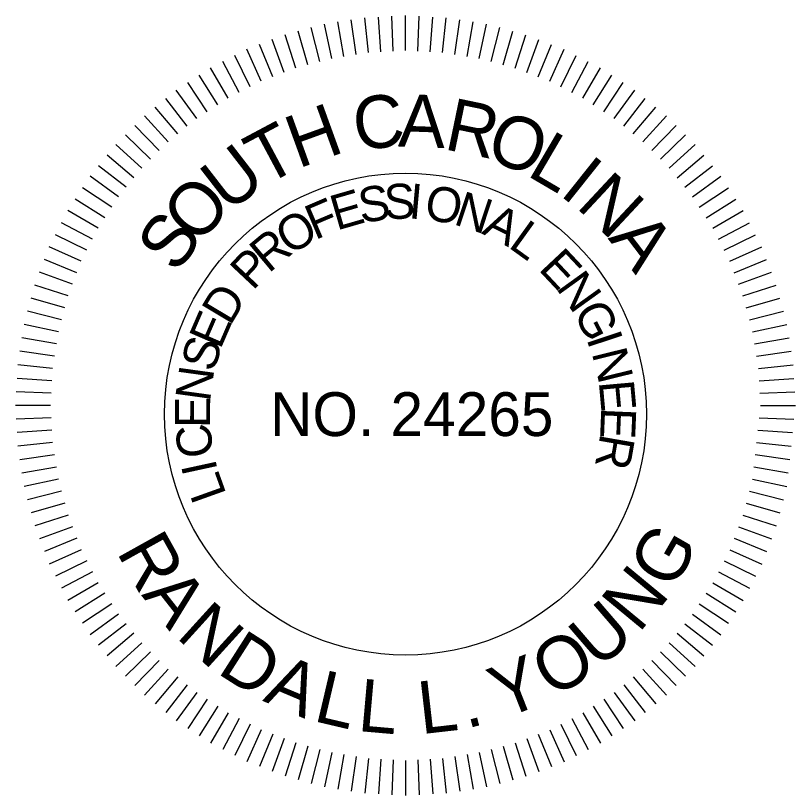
# Model space of a CAD drawing. Extents: x 1964849 to 1967422, y 1116563 to 1122211.
# Drawn here: x 1967342.1 to 1967421.3, y 1121681.4 to 1121760.6 of the extents above; entities that cross this region are included whole.
import ezdxf

# ---------------------------------------------------------------- set-up
doc = ezdxf.new("R2010")
doc.units = 0
doc.layers.add('RD_TX_PEShield', color=7, linetype='Continuous')

msp = doc.modelspace()

# ---------------------------------------------------------------- linework, layer by layer
at = {"layer": 'RD_TX_PEShield'}
for p, q in [((1967376.676, 1121756.687), (1967376.181, 1121760.208)), ((1967376.676, 1121756.687), (1967376.181, 1121760.208)), ((1967377.918, 1121756.884), (1967377.546, 1121760.424)), ((1967377.918, 1121756.884), (1967377.546, 1121760.424)), ((1967379.175, 1121756.949), (1967378.927, 1121760.496)), ((1967379.175, 1121756.949), (1967378.927, 1121760.496)), ((1967380.43, 1121757.015), (1967380.306, 1121760.569)), ((1967380.43, 1121757.015), (1967380.306, 1121760.569)), ((1967381.686, 1121757.081), (1967381.686, 1121760.641)), ((1967381.686, 1121757.081), (1967381.686, 1121760.641)), ((1967382.943, 1121757.015), (1967383.067, 1121760.569)), ((1967382.943, 1121757.015), (1967383.067, 1121760.569)), ((1967384.198, 1121756.949), (1967384.446, 1121760.496)), ((1967384.198, 1121756.949), (1967384.446, 1121760.496)), ((1967385.454, 1121756.884), (1967385.826, 1121760.424)), ((1967385.454, 1121756.884), (1967385.826, 1121760.424)), ((1967386.697, 1121756.687), (1967387.191, 1121760.208)), ((1967386.697, 1121756.687), (1967387.191, 1121760.208)), ((1967372.977, 1121755.968), (1967372.117, 1121759.418)), ((1967372.977, 1121755.968), (1967372.117, 1121759.418)), ((1967374.192, 1121756.293), (1967373.452, 1121759.776)), ((1967374.192, 1121756.293), (1967373.452, 1121759.776)), ((1967375.435, 1121756.49), (1967374.817, 1121759.992)), ((1967375.435, 1121756.49), (1967374.817, 1121759.992)), ((1967387.938, 1121756.49), (1967388.555, 1121759.992)), ((1967387.938, 1121756.49), (1967388.555, 1121759.992)), ((1967389.18, 1121756.293), (1967389.921, 1121759.776)), ((1967389.18, 1121756.293), (1967389.921, 1121759.776)), ((1967389.18, 1121756.293), (1967389.921, 1121759.776)), ((1967390.396, 1121755.968), (1967391.256, 1121759.418)), ((1967390.396, 1121755.968), (1967391.256, 1121759.418)), ((1967390.396, 1121755.968), (1967391.256, 1121759.418)), ((1967370.548, 1121755.317), (1967369.448, 1121758.703)), ((1967370.548, 1121755.317), (1967369.448, 1121758.703)), ((1967371.763, 1121755.642), (1967370.783, 1121759.06)), ((1967371.763, 1121755.642), (1967370.783, 1121759.06)), ((1967391.609, 1121755.642), (1967392.59, 1121759.06)), ((1967391.609, 1121755.642), (1967392.59, 1121759.06)), ((1967391.609, 1121755.642), (1967392.59, 1121759.06)), ((1967392.825, 1121755.317), (1967393.925, 1121758.703)), ((1967392.825, 1121755.317), (1967393.925, 1121758.703)), ((1967392.825, 1121755.317), (1967393.925, 1121758.703)), ((1967369.373, 1121754.866), (1967368.157, 1121758.207)), ((1967369.373, 1121754.866), (1967368.157, 1121758.207)), ((1967393.999, 1121754.866), (1967395.215, 1121758.207)), ((1967393.999, 1121754.866), (1967395.215, 1121758.207)), ((1967393.999, 1121754.866), (1967395.215, 1121758.207)), ((1967367.025, 1121753.965), (1967365.577, 1121757.217)), ((1967367.025, 1121753.965), (1967365.577, 1121757.217)), ((1967368.2, 1121754.416), (1967366.868, 1121757.712)), ((1967368.2, 1121754.416), (1967366.868, 1121757.712)), ((1967395.172, 1121754.416), (1967396.504, 1121757.712)), ((1967395.172, 1121754.416), (1967396.504, 1121757.712)), ((1967395.172, 1121754.416), (1967396.504, 1121757.712)), ((1967396.347, 1121753.965), (1967397.795, 1121757.217)), ((1967396.347, 1121753.965), (1967397.795, 1121757.217)), ((1967396.347, 1121753.965), (1967397.795, 1121757.217)), ((1967365.904, 1121753.394), (1967364.346, 1121756.589)), ((1967365.904, 1121753.394), (1967364.346, 1121756.589)), ((1967397.468, 1121753.394), (1967399.027, 1121756.589)), ((1967397.468, 1121753.394), (1967399.027, 1121756.589)), ((1967397.468, 1121753.394), (1967399.027, 1121756.589)), ((1967364.785, 1121752.823), (1967363.115, 1121755.963)), ((1967364.785, 1121752.823), (1967363.115, 1121755.963)), ((1967398.588, 1121752.823), (1967400.257, 1121755.963)), ((1967398.588, 1121752.823), (1967400.257, 1121755.963)), ((1967398.588, 1121752.823), (1967400.257, 1121755.963)), ((1967363.664, 1121752.252), (1967361.884, 1121755.335)), ((1967363.664, 1121752.252), (1967361.884, 1121755.335)), ((1967399.709, 1121752.252), (1967401.489, 1121755.335)), ((1967399.709, 1121752.252), (1967401.489, 1121755.335)), ((1967399.709, 1121752.252), (1967401.489, 1121755.335)), ((1967361.555, 1121750.882), (1967359.566, 1121753.83)), ((1967361.555, 1121750.882), (1967359.566, 1121753.83)), ((1967362.609, 1121751.567), (1967360.724, 1121754.582)), ((1967362.609, 1121751.567), (1967360.724, 1121754.582)), ((1967400.764, 1121751.567), (1967402.648, 1121754.582)), ((1967400.764, 1121751.567), (1967402.648, 1121754.582)), ((1967400.764, 1121751.567), (1967402.648, 1121754.582)), ((1967401.818, 1121750.882), (1967403.806, 1121753.83)), ((1967401.818, 1121750.882), (1967403.806, 1121753.83)), ((1967401.818, 1121750.882), (1967403.806, 1121753.83)), ((1967360.499, 1121750.197), (1967358.407, 1121753.077)), ((1967360.499, 1121750.197), (1967358.407, 1121753.077)), ((1967402.873, 1121750.197), (1967404.965, 1121753.077)), ((1967402.873, 1121750.197), (1967404.965, 1121753.077)), ((1967402.873, 1121750.197), (1967404.965, 1121753.077)), ((1967359.522, 1121749.405), (1967357.333, 1121752.207)), ((1967359.522, 1121749.405), (1967357.333, 1121752.207)), ((1967403.851, 1121749.405), (1967406.04, 1121752.207)), ((1967403.851, 1121749.405), (1967406.04, 1121752.207)), ((1967403.851, 1121749.405), (1967406.04, 1121752.207)), ((1967358.545, 1121748.614), (1967356.26, 1121751.338)), ((1967358.545, 1121748.614), (1967356.26, 1121751.338)), ((1967404.827, 1121748.614), (1967407.113, 1121751.338)), ((1967404.827, 1121748.614), (1967407.113, 1121751.338)), ((1967404.827, 1121748.614), (1967407.113, 1121751.338)), ((1967357.567, 1121747.823), (1967355.185, 1121750.468)), ((1967357.567, 1121747.823), (1967355.185, 1121750.468)), ((1967405.805, 1121747.823), (1967408.187, 1121750.468)), ((1967405.805, 1121747.823), (1967408.187, 1121750.468)), ((1967405.805, 1121747.823), (1967408.187, 1121750.468)), ((1967356.678, 1121746.933), (1967354.208, 1121749.491)), ((1967356.678, 1121746.933), (1967354.208, 1121749.491)), ((1967406.695, 1121746.933), (1967409.165, 1121749.491)), ((1967406.695, 1121746.933), (1967409.165, 1121749.491)), ((1967406.695, 1121746.933), (1967409.165, 1121749.491)), ((1967355.789, 1121746.044), (1967353.231, 1121748.514)), ((1967355.789, 1121746.044), (1967353.231, 1121748.514)), ((1967407.583, 1121746.044), (1967410.141, 1121748.514)), ((1967407.583, 1121746.044), (1967410.141, 1121748.514)), ((1967407.583, 1121746.044), (1967410.141, 1121748.514)), ((1967354.9, 1121745.155), (1967352.254, 1121747.537)), ((1967354.9, 1121745.155), (1967352.254, 1121747.537)), ((1967408.473, 1121745.155), (1967411.118, 1121747.537)), ((1967408.473, 1121745.155), (1967411.118, 1121747.537)), ((1967408.473, 1121745.155), (1967411.118, 1121747.537)), ((1967354.108, 1121744.177), (1967351.384, 1121746.463)), ((1967354.108, 1121744.177), (1967351.384, 1121746.463)), ((1967409.265, 1121744.177), (1967411.988, 1121746.463)), ((1967409.265, 1121744.177), (1967411.988, 1121746.463)), ((1967409.265, 1121744.177), (1967411.988, 1121746.463)), ((1967353.317, 1121743.2), (1967350.515, 1121745.39)), ((1967353.317, 1121743.2), (1967350.515, 1121745.39)), ((1967410.055, 1121743.2), (1967412.857, 1121745.39)), ((1967410.055, 1121743.2), (1967412.857, 1121745.39)), ((1967410.055, 1121743.2), (1967412.857, 1121745.39)), ((1967352.525, 1121742.223), (1967349.645, 1121744.315)), ((1967352.525, 1121742.223), (1967349.645, 1121744.315)), ((1967410.847, 1121742.223), (1967413.727, 1121744.315)), ((1967410.847, 1121742.223), (1967413.727, 1121744.315)), ((1967410.847, 1121742.223), (1967413.727, 1121744.315)), ((1967351.84, 1121741.168), (1967348.892, 1121743.156)), ((1967351.84, 1121741.168), (1967348.892, 1121743.156)), ((1967411.532, 1121741.168), (1967414.48, 1121743.156)), ((1967411.532, 1121741.168), (1967414.48, 1121743.156)), ((1967411.532, 1121741.168), (1967414.48, 1121743.156)), ((1967351.156, 1121740.114), (1967348.14, 1121741.998)), ((1967351.156, 1121740.114), (1967348.14, 1121741.998)), ((1967412.217, 1121740.114), (1967415.232, 1121741.998)), ((1967412.217, 1121740.114), (1967415.232, 1121741.998)), ((1967412.217, 1121740.114), (1967415.232, 1121741.998)), ((1967350.47, 1121739.058), (1967347.387, 1121740.838)), ((1967350.47, 1121739.058), (1967347.387, 1121740.838)), ((1967412.902, 1121739.058), (1967415.985, 1121740.838)), ((1967412.902, 1121739.058), (1967415.985, 1121740.838)), ((1967412.902, 1121739.058), (1967415.985, 1121740.838)), ((1967349.899, 1121737.937), (1967346.76, 1121739.607)), ((1967349.899, 1121737.937), (1967346.76, 1121739.607)), ((1967413.473, 1121737.937), (1967416.613, 1121739.607)), ((1967413.473, 1121737.937), (1967416.613, 1121739.607)), ((1967413.473, 1121737.937), (1967416.613, 1121739.607)), ((1967349.329, 1121736.818), (1967346.133, 1121738.377)), ((1967349.329, 1121736.818), (1967346.133, 1121738.377)), ((1967414.044, 1121736.818), (1967417.24, 1121738.377)), ((1967414.044, 1121736.818), (1967417.24, 1121738.377)), ((1967414.044, 1121736.818), (1967417.24, 1121738.377)), ((1967348.757, 1121735.697), (1967345.505, 1121737.145)), ((1967348.757, 1121735.697), (1967345.505, 1121737.145)), ((1967414.615, 1121735.697), (1967417.867, 1121737.145)), ((1967414.615, 1121735.697), (1967417.867, 1121737.145)), ((1967414.615, 1121735.697), (1967417.867, 1121737.145)), ((1967348.307, 1121734.522), (1967345.01, 1121735.854)), ((1967348.307, 1121734.522), (1967345.01, 1121735.854)), ((1967415.066, 1121734.522), (1967418.363, 1121735.854)), ((1967415.066, 1121734.522), (1967418.363, 1121735.854)), ((1967415.066, 1121734.522), (1967418.363, 1121735.854)), ((1967347.856, 1121733.349), (1967344.515, 1121734.565)), ((1967347.856, 1121733.349), (1967344.515, 1121734.565)), ((1967415.516, 1121733.349), (1967418.857, 1121734.565)), ((1967415.516, 1121733.349), (1967418.857, 1121734.565)), ((1967415.516, 1121733.349), (1967418.857, 1121734.565)), ((1967347.405, 1121732.174), (1967344.02, 1121733.275)), ((1967347.405, 1121732.174), (1967344.02, 1121733.275)), ((1967415.967, 1121732.174), (1967419.353, 1121733.275)), ((1967415.967, 1121732.174), (1967419.353, 1121733.275)), ((1967415.967, 1121732.174), (1967419.353, 1121733.275)), ((1967347.08, 1121730.959), (1967343.662, 1121731.939)), ((1967347.08, 1121730.959), (1967343.662, 1121731.939)), ((1967416.293, 1121730.959), (1967419.711, 1121731.939)), ((1967416.293, 1121730.959), (1967419.711, 1121731.939)), ((1967416.293, 1121730.959), (1967419.711, 1121731.939)), ((1967346.754, 1121729.745), (1967343.304, 1121730.606)), ((1967346.754, 1121729.745), (1967343.304, 1121730.606)), ((1967416.618, 1121729.745), (1967420.068, 1121730.606)), ((1967416.618, 1121729.745), (1967420.068, 1121730.606)), ((1967416.618, 1121729.745), (1967420.068, 1121730.606)), ((1967346.429, 1121728.53), (1967342.947, 1121729.27)), ((1967346.429, 1121728.53), (1967342.947, 1121729.27)), ((1967416.944, 1121728.53), (1967420.426, 1121729.27)), ((1967416.944, 1121728.53), (1967420.426, 1121729.27)), ((1967416.944, 1121728.53), (1967420.426, 1121729.27)), ((1967346.232, 1121727.287), (1967342.73, 1121727.905)), ((1967346.232, 1121727.287), (1967342.73, 1121727.905)), ((1967417.14, 1121727.287), (1967420.642, 1121727.905)), ((1967417.14, 1121727.287), (1967420.642, 1121727.905)), ((1967417.14, 1121727.287), (1967420.642, 1121727.905)), ((1967346.035, 1121726.046), (1967342.514, 1121726.541)), ((1967346.035, 1121726.046), (1967342.514, 1121726.541)), ((1967417.337, 1121726.046), (1967420.858, 1121726.541)), ((1967417.337, 1121726.046), (1967420.858, 1121726.541)), ((1967417.337, 1121726.046), (1967420.858, 1121726.541)), ((1967345.839, 1121724.804), (1967342.298, 1121725.176)), ((1967345.839, 1121724.804), (1967342.298, 1121725.176)), ((1967417.534, 1121724.804), (1967421.074, 1121725.176)), ((1967417.534, 1121724.804), (1967421.074, 1121725.176)), ((1967417.534, 1121724.804), (1967421.074, 1121725.176)), ((1967345.773, 1121723.547), (1967342.226, 1121723.795)), ((1967345.773, 1121723.547), (1967342.226, 1121723.795)), ((1967417.6, 1121723.547), (1967421.147, 1121723.795)), ((1967417.6, 1121723.547), (1967421.147, 1121723.795)), ((1967417.6, 1121723.547), (1967421.147, 1121723.795)), ((1967345.707, 1121722.292), (1967342.154, 1121722.416)), ((1967345.707, 1121722.292), (1967342.154, 1121722.416)), ((1967417.665, 1121722.292), (1967421.219, 1121722.416)), ((1967417.665, 1121722.292), (1967421.219, 1121722.416)), ((1967417.665, 1121722.292), (1967421.219, 1121722.416)), ((1967345.641, 1121721.036), (1967342.081, 1121721.036)), ((1967345.641, 1121721.036), (1967342.081, 1121721.036)), ((1967417.731, 1121721.036), (1967421.291, 1121721.036)), ((1967417.731, 1121721.036), (1967421.291, 1121721.036)), ((1967417.731, 1121721.036), (1967421.291, 1121721.036)), ((1967345.707, 1121719.78), (1967342.154, 1121719.655)), ((1967345.707, 1121719.78), (1967342.154, 1121719.655)), ((1967417.599, 1121719.782), (1967421.146, 1121719.658)), ((1967417.599, 1121719.782), (1967421.146, 1121719.658)), ((1967345.773, 1121718.525), (1967342.226, 1121718.277)), ((1967345.773, 1121718.525), (1967342.226, 1121718.277)), ((1967417.468, 1121718.534), (1967421.002, 1121718.287)), ((1967417.468, 1121718.534), (1967421.002, 1121718.287)), ((1967345.839, 1121717.268), (1967342.298, 1121716.896)), ((1967345.839, 1121717.268), (1967342.298, 1121716.896)), ((1967417.337, 1121717.289), (1967420.858, 1121716.919)), ((1967417.337, 1121717.289), (1967420.858, 1121716.919)), ((1967346.035, 1121716.026), (1967342.514, 1121715.531)), ((1967346.035, 1121716.026), (1967342.514, 1121715.531)), ((1967417.207, 1121716.044), (1967420.715, 1121715.551)), ((1967417.207, 1121716.044), (1967420.715, 1121715.551)), ((1967346.232, 1121714.784), (1967342.73, 1121714.167)), ((1967346.232, 1121714.784), (1967342.73, 1121714.167)), ((1967417.075, 1121714.796), (1967420.571, 1121714.18)), ((1967417.075, 1121714.796), (1967420.571, 1121714.18)), ((1967346.429, 1121713.542), (1967342.947, 1121712.802)), ((1967346.429, 1121713.542), (1967342.947, 1121712.802)), ((1967416.944, 1121713.542), (1967420.426, 1121712.802)), ((1967416.944, 1121713.542), (1967420.426, 1121712.802)), ((1967346.754, 1121712.327), (1967343.304, 1121711.466)), ((1967346.754, 1121712.327), (1967343.304, 1121711.466)), ((1967416.618, 1121712.327), (1967420.068, 1121711.466)), ((1967416.618, 1121712.327), (1967420.068, 1121711.466)), ((1967347.08, 1121711.113), (1967343.662, 1121710.133)), ((1967347.08, 1121711.113), (1967343.662, 1121710.133)), ((1967416.293, 1121711.113), (1967419.711, 1121710.133)), ((1967416.293, 1121711.113), (1967419.711, 1121710.133)), ((1967347.405, 1121709.897), (1967344.02, 1121708.797)), ((1967415.967, 1121709.897), (1967419.353, 1121708.797)), ((1967415.967, 1121709.897), (1967419.353, 1121708.797)), ((1967347.856, 1121708.723), (1967344.515, 1121707.507)), ((1967347.856, 1121708.723), (1967344.515, 1121707.507)), ((1967415.516, 1121708.723), (1967418.857, 1121707.507)), ((1967415.516, 1121708.723), (1967418.857, 1121707.507)), ((1967348.307, 1121707.55), (1967345.01, 1121706.218)), ((1967348.307, 1121707.55), (1967345.01, 1121706.218)), ((1967415.066, 1121707.55), (1967418.363, 1121706.218)), ((1967415.066, 1121707.55), (1967418.363, 1121706.218)), ((1967348.757, 1121706.375), (1967345.505, 1121704.927)), ((1967348.757, 1121706.375), (1967345.505, 1121704.927)), ((1967414.615, 1121706.375), (1967417.867, 1121704.927)), ((1967414.615, 1121706.375), (1967417.867, 1121704.927)), ((1967349.329, 1121705.254), (1967346.133, 1121703.695)), ((1967349.329, 1121705.254), (1967346.133, 1121703.695)), ((1967414.044, 1121705.254), (1967417.24, 1121703.695)), ((1967414.044, 1121705.254), (1967417.24, 1121703.695)), ((1967349.899, 1121704.134), (1967346.76, 1121702.465)), ((1967349.899, 1121704.134), (1967346.76, 1121702.465)), ((1967413.473, 1121704.134), (1967416.613, 1121702.465)), ((1967413.473, 1121704.134), (1967416.613, 1121702.465)), ((1967350.47, 1121703.013), (1967347.387, 1121701.233)), ((1967350.47, 1121703.013), (1967347.387, 1121701.233)), ((1967412.902, 1121703.013), (1967415.985, 1121701.233)), ((1967412.902, 1121703.013), (1967415.985, 1121701.233)), ((1967351.156, 1121701.958), (1967348.14, 1121700.074)), ((1967351.156, 1121701.958), (1967348.14, 1121700.074)), ((1967412.217, 1121701.958), (1967415.232, 1121700.074)), ((1967412.217, 1121701.958), (1967415.232, 1121700.074)), ((1967351.84, 1121700.904), (1967348.892, 1121698.916)), ((1967351.84, 1121700.904), (1967348.892, 1121698.916)), ((1967411.532, 1121700.904), (1967414.48, 1121698.916)), ((1967411.532, 1121700.904), (1967414.48, 1121698.916)), ((1967352.525, 1121699.849), (1967349.645, 1121697.757)), ((1967352.525, 1121699.849), (1967349.645, 1121697.757)), ((1967410.847, 1121699.849), (1967413.727, 1121697.757)), ((1967410.847, 1121699.849), (1967413.727, 1121697.757)), ((1967353.317, 1121698.871), (1967350.515, 1121696.682)), ((1967353.317, 1121698.871), (1967350.515, 1121696.682)), ((1967410.055, 1121698.871), (1967412.857, 1121696.682)), ((1967410.055, 1121698.871), (1967412.857, 1121696.682)), ((1967354.108, 1121697.895), (1967351.384, 1121695.609)), ((1967354.108, 1121697.895), (1967351.384, 1121695.609)), ((1967409.265, 1121697.895), (1967411.988, 1121695.609)), ((1967409.265, 1121697.895), (1967411.988, 1121695.609)), ((1967354.9, 1121696.917), (1967352.254, 1121694.535)), ((1967354.9, 1121696.917), (1967352.254, 1121694.535)), ((1967408.473, 1121696.917), (1967411.118, 1121694.535)), ((1967408.473, 1121696.917), (1967411.118, 1121694.535)), ((1967355.789, 1121696.028), (1967353.231, 1121693.558)), ((1967355.789, 1121696.028), (1967353.231, 1121693.558)), ((1967407.583, 1121696.028), (1967410.141, 1121693.558)), ((1967407.583, 1121696.028), (1967410.141, 1121693.558)), ((1967356.678, 1121695.139), (1967354.208, 1121692.581)), ((1967356.678, 1121695.139), (1967354.208, 1121692.581)), ((1967406.695, 1121695.139), (1967409.165, 1121692.581)), ((1967406.695, 1121695.139), (1967409.165, 1121692.581)), ((1967357.567, 1121694.249), (1967355.185, 1121691.604)), ((1967357.567, 1121694.249), (1967355.185, 1121691.604)), ((1967405.805, 1121694.249), (1967408.187, 1121691.604)), ((1967358.545, 1121693.458), (1967356.26, 1121690.734)), ((1967358.545, 1121693.458), (1967356.26, 1121690.734)), ((1967404.827, 1121693.458), (1967407.113, 1121690.734)), ((1967404.827, 1121693.458), (1967407.113, 1121690.734)), ((1967359.522, 1121692.667), (1967357.333, 1121689.865)), ((1967359.522, 1121692.667), (1967357.333, 1121689.865)), ((1967403.851, 1121692.667), (1967406.04, 1121689.865)), ((1967403.851, 1121692.667), (1967406.04, 1121689.865)), ((1967360.499, 1121691.875), (1967358.407, 1121688.995)), ((1967360.499, 1121691.875), (1967358.407, 1121688.995)), ((1967402.873, 1121691.875), (1967404.965, 1121688.995)), ((1967402.873, 1121691.875), (1967404.965, 1121688.995)), ((1967361.555, 1121691.19), (1967359.566, 1121688.242)), ((1967361.555, 1121691.19), (1967359.566, 1121688.242)), ((1967362.609, 1121690.505), (1967360.724, 1121687.49)), ((1967362.609, 1121690.505), (1967360.724, 1121687.49)), ((1967400.764, 1121690.505), (1967402.648, 1121687.49)), ((1967400.764, 1121690.505), (1967402.648, 1121687.49)), ((1967401.818, 1121691.19), (1967403.806, 1121688.242)), ((1967401.818, 1121691.19), (1967403.806, 1121688.242)), ((1967363.664, 1121689.82), (1967361.884, 1121686.737)), ((1967363.664, 1121689.82), (1967361.884, 1121686.737)), ((1967399.709, 1121689.82), (1967401.489, 1121686.737)), ((1967399.709, 1121689.82), (1967401.489, 1121686.737)), ((1967364.785, 1121689.249), (1967363.115, 1121686.109)), ((1967364.785, 1121689.249), (1967363.115, 1121686.109)), ((1967398.588, 1121689.249), (1967400.257, 1121686.109)), ((1967398.588, 1121689.249), (1967400.257, 1121686.109)), ((1967365.904, 1121688.678), (1967364.346, 1121685.483)), ((1967365.904, 1121688.678), (1967364.346, 1121685.483)), ((1967367.025, 1121688.107), (1967365.577, 1121684.855)), ((1967367.025, 1121688.107), (1967365.577, 1121684.855)), ((1967396.347, 1121688.107), (1967397.795, 1121684.855)), ((1967396.347, 1121688.107), (1967397.795, 1121684.855)), ((1967397.468, 1121688.678), (1967399.027, 1121685.483)), ((1967397.468, 1121688.678), (1967399.027, 1121685.483)), ((1967368.2, 1121687.656), (1967366.868, 1121684.36)), ((1967368.2, 1121687.656), (1967366.868, 1121684.36)), ((1967395.172, 1121687.656), (1967396.504, 1121684.36)), ((1967395.172, 1121687.656), (1967396.504, 1121684.36)), ((1967369.373, 1121687.206), (1967368.157, 1121683.865)), ((1967369.373, 1121687.206), (1967368.157, 1121683.865)), ((1967370.548, 1121686.755), (1967369.448, 1121683.369)), ((1967370.548, 1121686.755), (1967369.448, 1121683.369)), ((1967392.825, 1121686.755), (1967393.925, 1121683.369)), ((1967392.825, 1121686.755), (1967393.925, 1121683.369)), ((1967393.999, 1121687.206), (1967395.215, 1121683.865)), ((1967393.999, 1121687.206), (1967395.215, 1121683.865)), ((1967371.763, 1121686.43), (1967370.783, 1121683.012)), ((1967371.763, 1121686.43), (1967370.783, 1121683.012)), ((1967372.977, 1121686.104), (1967372.117, 1121682.654)), ((1967372.977, 1121686.104), (1967372.117, 1121682.654)), ((1967374.192, 1121685.779), (1967373.452, 1121682.296)), ((1967374.192, 1121685.779), (1967373.452, 1121682.296)), ((1967389.18, 1121685.779), (1967389.921, 1121682.296)), ((1967389.18, 1121685.779), (1967389.921, 1121682.296)), ((1967390.396, 1121686.104), (1967391.256, 1121682.654)), ((1967390.396, 1121686.104), (1967391.256, 1121682.654)), ((1967391.609, 1121686.43), (1967392.59, 1121683.012)), ((1967391.609, 1121686.43), (1967392.59, 1121683.012)), ((1967375.435, 1121685.582), (1967374.817, 1121682.08)), ((1967375.435, 1121685.582), (1967374.817, 1121682.08)), ((1967376.676, 1121685.385), (1967376.181, 1121681.864)), ((1967376.676, 1121685.385), (1967376.181, 1121681.864)), ((1967377.918, 1121685.188), (1967377.546, 1121681.648)), ((1967377.918, 1121685.188), (1967377.546, 1121681.648)), ((1967379.175, 1121685.123), (1967378.927, 1121681.576)), ((1967379.175, 1121685.123), (1967378.927, 1121681.576)), ((1967380.43, 1121685.057), (1967380.306, 1121681.503)), ((1967380.43, 1121685.057), (1967380.306, 1121681.503)), ((1967381.686, 1121684.991), (1967381.686, 1121681.431)), ((1967381.686, 1121684.991), (1967381.686, 1121681.431)), ((1967382.943, 1121685.057), (1967383.067, 1121681.503)), ((1967382.943, 1121685.057), (1967383.067, 1121681.503)), ((1967384.198, 1121685.123), (1967384.446, 1121681.576)), ((1967384.198, 1121685.123), (1967384.446, 1121681.576)), ((1967385.454, 1121685.188), (1967385.826, 1121681.648)), ((1967385.454, 1121685.188), (1967385.826, 1121681.648)), ((1967386.697, 1121685.385), (1967387.191, 1121681.864)), ((1967386.697, 1121685.385), (1967387.191, 1121681.864)), ((1967387.938, 1121685.582), (1967388.555, 1121682.08)), ((1967387.938, 1121685.582), (1967388.555, 1121682.08))]:
    msp.add_line(p, q, dxfattribs=at)
msp.add_circle((1967381.686, 1121720.158), 24.475, dxfattribs=at)

# ---------------------------------------------------------------- texts
for s, height, rotation, p in [('C', 5.34, 6.88322, (1967376.68, 1121746.896)), ('A', 5.34, 357.94482, (1967380.895, 1121747.349)), ('H', 5.34, 19.91024, (1967370.782, 1121745.079)), ('R', 5.34, 348.26699, (1967385.478, 1121747.095)), ('O', 5.34, 339.32858, (1967389.617, 1121746.178)), ('T', 5.34, 28.09472, (1967367.345, 1121743.273)), ('L', 5.34, 329.65075, (1967393.878, 1121744.475)), ('U', 5.34, 37.77255, (1967363.664, 1121740.533)), ('I', 5.34, 321.46627, (1967397.216, 1121742.492)), ('N', 5.34, 317.00069, (1967398.908, 1121741.215)), ('O', 5.34, 47.45038, (1967360.495, 1121737.214)), ('S', 3.56, 1.78995, (1967379.536, 1121739.948)), ('I', 3.56, 354.88899, (1967381.93, 1121740.062)), ('E', 3.56, 16.18428, (1967374.684, 1121738.792)), ('S', 3.56, 8.69092, (1967377.174, 1121739.546)), ('O', 3.56, 350.40454, (1967383.485, 1121739.982)), ('N', 3.56, 341.70291, (1967386.464, 1121739.482)), ('F', 3.56, 23.08525, (1967372.496, 1121737.816)), ('S', 5.34, 54.90268, (1967358.462, 1121734.321)), ('O', 3.56, 31.78688, (1967369.93, 1121736.222)), ('A', 3.56, 333.00129, (1967389.332, 1121738.537)), ('L', 3.56, 324.29966, (1967392.025, 1121737.169)), ('A', 5.34, 307.32286, (1967402.202, 1121738.02)), ('R', 3.56, 39.89024, (1967367.783, 1121734.404)), ('P', 3.56, 46.7912, (1967366.172, 1121732.631)), ('E', 3.56, 313.22511, (1967395.1, 1121734.866)), ('N', 3.56, 305.73175, (1967396.903, 1121732.991)), ('D', 3.56, 59.07401, (1967363.874, 1121729.045)), ('G', 3.56, 297.03012, (1967398.67, 1121730.541)), ('E', 3.56, 66.56738, (1967362.867, 1121726.646)), ('I', 3.56, 288.3285, (1967400.045, 1121727.852)), ('S', 3.56, 73.46834, (1967362.224, 1121724.338)), ('N', 3.56, 283.84405, (1967400.59, 1121726.393)), ('N', 3.56, 82.16997, (1967361.816, 1121721.345)), ('E', 3.56, 275.14243, (1967401.316, 1121723.461)), ('E', 3.56, 89.66334, (1967361.83, 1121718.744)), ('E', 3.56, 267.64906, (1967401.579, 1121720.873)), ('C', 3.56, 97.7667, (1967362.228, 1121715.959)), ('R', 3.56, 260.15569, (1967401.503, 1121718.273)), ('I', 3.56, 102.25114, (1967362.616, 1121714.451)), ('L', 3.56, 109.74451, (1967363.523, 1121712.012)), ('R', 5.34, 299.14926, (1967352.284, 1121706.184)), ('G', 5.34, 60.11131, (1967408.795, 1121702.134)), ('N', 5.34, 50.43348, (1967405.38, 1121697.834)), ('A', 5.34, 308.08766, (1967354.812, 1121701.786)), ('N', 5.34, 317.7655, (1967358.283, 1121697.529)), ('U', 5.34, 40.75564, (1967401.29, 1121694.168)), ('D', 5.34, 327.44333, (1967362.42, 1121693.917)), ('O', 5.34, 31.07781, (1967396.642, 1121691.243)), ('A', 5.34, 337.12116, (1967367.106, 1121691.052)), ('Y', 5.34, 21.39998, (1967391.568, 1121689.14)), ('L', 5.34, 346.799, (1967372.206, 1121689.015)), ('L', 5.34, 354.98347, (1967376.736, 1121687.982)), ('L', 5.34, 6.51713, (1967383.27, 1121687.642)), ('.', 5.34, 14.70161, (1967387.882, 1121688.199))]:
    msp.add_text(s, height=height, rotation=rotation, dxfattribs=at).set_placement(p)
msp.add_text('NO. 24265', height=4.4501, dxfattribs=at).set_placement((1967367.932, 1121717.933))

doc.saveas('drawing.dxf')
